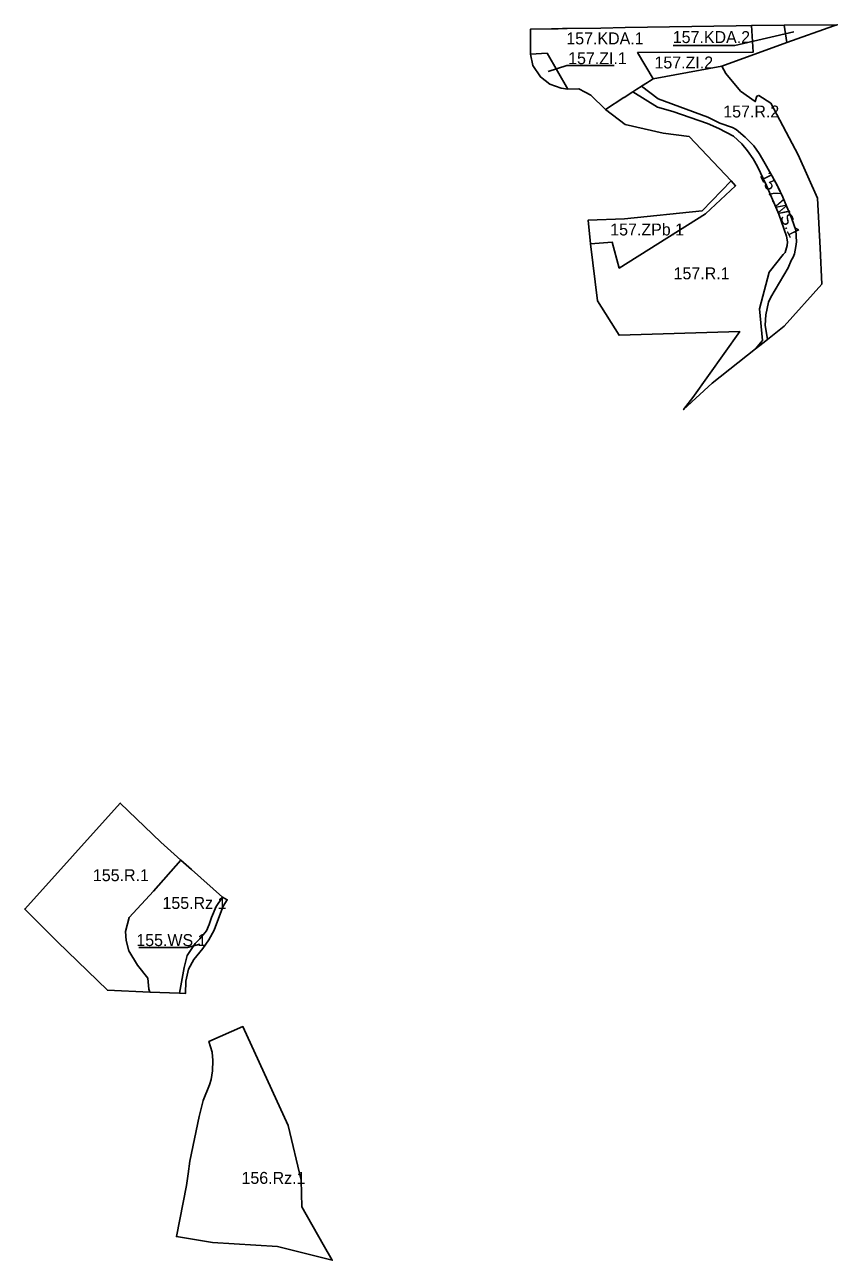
# Model space of a CAD drawing. Extents: x 7429182 to 7430853, y 5540984 to 5542492.
# Drawn here: x 7430325 to 7430665, y 5540984 to 5541502 of the extents above; entities that cross this region are included whole.
import ezdxf

# ---------------------------------------------------------------- set-up
doc = ezdxf.new("R2010")
doc.units = 0
doc.layers.add('LIN_Linie Rozgraniczajace', color=7, linetype='Continuous')
doc.layers.add('TXT_Oznaczenia Przeznaczenia', color=7, linetype='Continuous')

msp = doc.modelspace()

# ---------------------------------------------------------------- linework, layer by layer
at = {"layer": 'LIN_Linie Rozgraniczajace'}
for p, q in [((7430642.46, 5541501.37), (7430628.77, 5541501.23)), ((7430643.62, 5541494.21), (7430642.46, 5541501.37)), ((7430616.34, 5541484.28), (7430643.62, 5541494.21)), ((7430616.34, 5541484.28), (7430587.68, 5541478.95)), ((7430389.36, 5541096.09), (7430376.97, 5541096.6))]:
    msp.add_line(p, q, dxfattribs=at)
for points in [[(7430628.77, 5541501.23), (7430622.39, 5541501.17), (7430575.91, 5541500.36), (7430565.76, 5541500.2), (7430551.6, 5541499.98), (7430549.76, 5541499.95), (7430547.94, 5541499.92), (7430545.04, 5541499.87), (7430536.34, 5541499.74), (7430536.37, 5541489.29), (7430536.37, 5541489.29)], [(7430587.68, 5541478.95), (7430581.11, 5541489.91), (7430629.53, 5541490.11), (7430628.77, 5541501.23)], [(7430643.62, 5541494.21), (7430663.31, 5541501.1), (7430664.71, 5541501.59), (7430642.46, 5541501.37)], [(7430536.37, 5541489.29), (7430543.27, 5541489.69), (7430551.88, 5541474.66)], [(7430551.88, 5541474.66), (7430549.21, 5541474.99), (7430544.41, 5541476.64), (7430540.46, 5541479.71), (7430537.33, 5541484.49), (7430536.37, 5541489.29)], [(7430616.34, 5541484.28), (7430618.07, 5541481.22), (7430624.24, 5541473.7), (7430630.38, 5541469.42), (7430631.08, 5541471.62), (7430631.94, 5541471.99), (7430636.85, 5541468.73), (7430648.4, 5541447.06), (7430656.42, 5541428.93), (7430657.54, 5541408.07), (7430658.31, 5541393.01), (7430642.5, 5541375.32), (7430635.56, 5541369.84), (7430635.46, 5541369.76)], [(7430587.68, 5541478.95), (7430586.17, 5541477.99), (7430585.35, 5541477.46), (7430582.83, 5541475.85)], [(7430567.67, 5541466.14), (7430567.67, 5541466.14), (7430561.6, 5541472.13), (7430559.26, 5541473.35), (7430556.51, 5541474.76), (7430551.88, 5541474.66)], [(7430567.67, 5541466.14), (7430575.34, 5541471.05), (7430575.45, 5541471.12), (7430579.17, 5541473.51)], [(7430582.83, 5541475.85), (7430582.67, 5541475.75), (7430580.83, 5541474.57), (7430579.17, 5541473.51)], [(7430630.46, 5541365.84), (7430633.4, 5541369.4), (7430632.18, 5541382.69), (7430636.21, 5541398.03), (7430642, 5541405.4), (7430642.88, 5541406.18), (7430643.8, 5541409.13), (7430643.91, 5541410.7), (7430643.39, 5541413.06), (7430640.21, 5541422.27), (7430635.02, 5541434.2), (7430631.29, 5541442.19), (7430629.46, 5541445.37), (7430627.17, 5541448.82), (7430624.7, 5541451.76), (7430621.22, 5541454.87), (7430615.19, 5541458.07), (7430610.39, 5541460.27), (7430595.93, 5541465.28), (7430589.47, 5541467.01), (7430579.17, 5541473.51)], [(7430635.46, 5541369.76), (7430634.59, 5541375.84), (7430634.75, 5541380.13), (7430635.87, 5541385.44), (7430636.85, 5541387.54), (7430644.2, 5541399.81), (7430645.39, 5541402.82), (7430646.2, 5541404.28), (7430646.76, 5541405.71), (7430647.36, 5541408.75), (7430647.65, 5541410.67), (7430647.31, 5541415.52), (7430645.68, 5541420.26), (7430641.93, 5541429.41), (7430639.88, 5541433.87), (7430637.41, 5541438.17), (7430633.41, 5541445.36), (7430632.01, 5541447.62), (7430629.72, 5541450.91), (7430626.2, 5541454.53), (7430622.46, 5541457.72), (7430620.92, 5541458.5), (7430615.62, 5541460.4), (7430610.52, 5541462.91), (7430589.69, 5541470.57), (7430582.83, 5541475.85)], [(7430620.24, 5541436.16), (7430602.68, 5541454.78), (7430591.8, 5541456.21), (7430575.89, 5541459.78), (7430567.67, 5541466.14)], [(7430561.47, 5541409.89), (7430560.48, 5541419.82), (7430575.59, 5541420.38), (7430608.12, 5541423.67), (7430620.24, 5541436.16)], [(7430620.24, 5541436.16), (7430622.12, 5541434.17), (7430609.59, 5541422.39), (7430573.44, 5541399.67), (7430570.45, 5541410.57), (7430561.47, 5541409.89)], [(7430561.47, 5541409.89), (7430564.31, 5541385.95), (7430573.4, 5541371.58), (7430623.87, 5541373.12), (7430604.31, 5541345.54), (7430600.39, 5541340.43), (7430612.35, 5541351.56), (7430630.46, 5541365.84)], [(7430630.46, 5541365.84), (7430633.5, 5541368.24), (7430635.46, 5541369.76)], [(7430390, 5541151.85), (7430381.57, 5541159.37), (7430364.59, 5541175.67), (7430324.64, 5541131.34), (7430324.64, 5541131.34), (7430338.35, 5541117.55), (7430359.24, 5541097.33), (7430376.97, 5541096.6)], [(7430390, 5541151.85), (7430378.47, 5541138.89), (7430368.28, 5541127.81), (7430366.8, 5541121.87), (7430367.1, 5541118.2), (7430368.16, 5541113.88), (7430371.82, 5541107.82), (7430376.14, 5541102.42), (7430376.63, 5541097.75), (7430376.97, 5541096.6)], [(7430407.4, 5541136.34), (7430394.49, 5541147.85), (7430390, 5541151.85)], [(7430389.36, 5541096.09), (7430391.93, 5541095.99), (7430392.02, 5541101.1), (7430393.12, 5541106.12), (7430395.4, 5541110.19), (7430399.17, 5541114.79), (7430401.66, 5541118.43), (7430403.92, 5541122.43), (7430406.17, 5541128.55), (7430407.68, 5541132.48), (7430409.37, 5541135.2), (7430407.4, 5541136.34)], [(7430407.4, 5541136.34), (7430404.78, 5541132.39), (7430402.75, 5541127.77), (7430401.82, 5541124.87), (7430400.75, 5541122.23), (7430397.97, 5541118.83), (7430395.98, 5541116.94), (7430392.62, 5541111.89), (7430391.3, 5541106.91), (7430389.36, 5541096.09)], [(7430449.58, 5540990.92), (7430440.58, 5541006.69), (7430440.27, 5541017.78), (7430434.89, 5541040.75), (7430415.99, 5541082.1), (7430401.76, 5541075.94), (7430403.14, 5541071.44), (7430403.33, 5541067.88), (7430403.26, 5541063.6), (7430402.65, 5541060.04), (7430401.93, 5541057.73), (7430399.28, 5541051.18), (7430397.6, 5541044.51), (7430393.79, 5541025.77), (7430393.03, 5541020.45), (7430392.36, 5541015.56), (7430388.13, 5540994.17), (7430403.19, 5540991.73), (7430430.37, 5540990.02), (7430453.37, 5540984.28), (7430449.58, 5540990.92)]]:
    msp.add_lwpolyline(points, dxfattribs=at)
at = {"layer": 'TXT_Oznaczenia Przeznaczenia'}
for points in [[(7430595.99, 5541492.95), (7430621.86, 5541492.95), (7430646.47, 5541498.59)], [(7430571.33, 5541484.47), (7430551.49, 5541484.47), (7430543.65, 5541482.06)], [(7430372.36, 5541115.2), (7430392.82, 5541115.29), (7430397.94, 5541116.65)]]:
    msp.add_lwpolyline(points, dxfattribs=at)

# ---------------------------------------------------------------- texts
for s, p in [('157.KDA.2', (7430595.86, 5541493.91)), ('157.KDA.1', (7430551.31, 5541493.36)), ('157.ZI.1', (7430552.08, 5541485.07)), ('157.ZI.2', (7430588.21, 5541483.27)), ('157.R.2', (7430617, 5541462.75)), ('157.ZPb.1', (7430569.7, 5541413.35)), ('157.R.1', (7430596.21, 5541394.99)), ('155.R.1', (7430353.18, 5541143.01)), ('155.Rz.1', (7430382.29, 5541131.39)), ('155.WS.1', (7430371.35, 5541115.84)), ('156.Rz.1', (7430415.37, 5541016.27))]:
    msp.add_text(s, height=5, dxfattribs=at).set_placement(p)
msp.add_text('157.WS.1', height=5, rotation=295.9168, dxfattribs=at).set_placement((7430632.15, 5541438.43))

doc.saveas('drawing.dxf')
